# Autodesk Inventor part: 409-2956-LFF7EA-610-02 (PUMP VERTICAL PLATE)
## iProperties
Created: 2011-01
Part Number: 409-2956-LFF7EA-610-02 (PUMP VERTICAL PLATE)
Cost Center: 0 lbmass
Material: A36 STEEL PLATE
Document SubType Name: Sheet Metal
Designer: S. Boerckel
Authority: 0 in^3
Mass: 1949.37 g
Surface Area: 1086.35 cm^2
Volume: 248.011 cm^3
Density: 7.86 g/cm^3
Flat Pattern Width: 17.78 cm
Flat Pattern Length: 29.1252 cm
Flat Pattern Area: 517.846 cm^2
Sheet Metal Rule: 3/16"Thk
Author: S. Boerckel
Revision Number: 0
SaveDate: 2008-01-15
SaveTime: 10:24
FileName: Sheet Metal
Wide: =<Flat Pattern Width>cm
Length: =<Flat Pattern Length>cm
Thickness: 0.1875 in
SMR: =<Sheet Metal Rule> - <Material>
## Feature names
1. Plate1
2. Plate2
3. Bend1
